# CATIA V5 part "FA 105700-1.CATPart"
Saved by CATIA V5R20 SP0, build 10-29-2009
Part number: FA 105700-1
Revision: ANY
Definition: UNKNOWN
Nomenclature: FA 105700-1
Source: Unknown
Bounding box of the stored display mesh (mm): x -2.853 to 2.853, y 0.2 to 2.5, z -3 to 3
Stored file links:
  C:\Users\Utente\Desktop\IO LAVORO\3D X SITO CF\CUMSA\3D files FA\FA 1057SF\FA 105700-1.CATPart

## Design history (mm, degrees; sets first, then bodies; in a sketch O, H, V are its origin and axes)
Body1 "Cortar-Extruir1" (main body)
  Solid1: solid without history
